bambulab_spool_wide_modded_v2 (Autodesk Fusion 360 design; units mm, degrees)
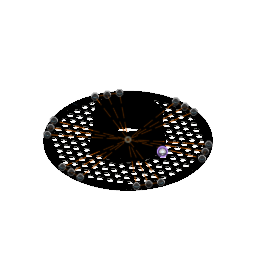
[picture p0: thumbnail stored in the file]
parameter "lattice_diameter" = 10.25
parameter "lattice_thickness" = 3.75
parameter "hole_diameter" = 3.5 comment "Hole Diameter of the rim"
base_mesh_feature "Base Mesh Feature"
convert_mesh "Convert Mesh" bodies "bambulab_spool_wide"
sketch "Sketch13" plane through (0, 0, -16.75) normal (0, 0, 1) x axis (-1, 0, 0)
  line L1 (92.6217, -5.7502) -> (99.4206, -5.9753)
  line L2 (92.483, -7.6633) -> (92.6217, -5.7502)
  line L3 (99.4206, -5.9753) -> (92.483, -7.6633)
  line L4 (0, 0) -> (-74.6153, -60.4003)
  line L5 (-89.6135, -34.4171) -> (0, 0)
  line L6 (-74.6153, -60.4003) -> (-89.6135, -34.4171)
  line L7 (-15.0006, -94.8162) -> (0, 0)
  line L8 (15.0006, -94.8189) -> (-15.0006, -94.8162)
  line L9 (0, 0) -> (15.0006, -94.8189)
  line L10 (0, 0) -> (74.6129, -60.399)
  line L11 (0, 0) -> (89.6159, -34.4185)
  line L12 (74.6129, -60.399) -> (89.6159, -34.4185)
  line L13 (89.6135, 34.4171) -> (0, 0)
  line L14 (74.6153, 60.4003) -> (89.6135, 34.4171)
  line L15 (0, 0) -> (74.6153, 60.4003)
  line L16 (0, 0) -> (-15.0006, 94.8189)
  line L17 (15.0006, 94.8162) -> (-15.0006, 94.8189)
  line L18 (0, 0) -> (15.0006, 94.8162)
  line L19 (0, 0) -> (-89.6159, 34.4185)
  line L20 (-89.6159, 34.4185) -> (-74.6129, 60.399)
  line L21 (0, 0) -> (-74.6129, 60.399)
  line L22 (0, 0) -> (-82.1144, 47.4088)
  line L23 (0, 0) -> (0, 94.8175)
  line L24 (0, 0) -> (82.1144, 47.4087)
  line L25 (0, 0) -> (82.1144, -47.4088)
  line L26 (0, 0) -> (0, -94.8175)
  line L27 (0, 0) -> (-82.1144, -47.4087)
  circle C1 centre (15.0006, -94.8189) radius 2
  circle C2 centre (-15.0006, -94.8162) radius 2
  circle C3 centre (89.6159, -34.4185) radius 2
  circle C4 centre (74.6153, 60.4003) radius 2
  circle C5 centre (-15.0006, 94.8189) radius 2
  circle C6 centre (-89.6159, 34.4185) radius 2
  circle C7 centre (-74.6153, -60.4003) radius 2
  circle C8 centre (74.6129, -60.399) radius 2
  circle C9 centre (89.6135, 34.4171) radius 2
  circle C10 centre (15.0006, 94.8162) radius 2
  circle C11 centre (-74.6129, 60.399) radius 2
  circle C12 centre (-89.6135, -34.4171) radius 2
  point P1 (0, 0)
  point P7 (0, 0)
  point P12 (-74.6153, -60.4003)
  point P18 (-74.6153, -60.4003)
  point P19 (0, 0)
  point P17 (-89.6135, -34.4171)
  point P20 (-89.6135, -34.4171)
  point P21 (-74.6153, -60.4003)
  point P22 (-82.1144, -47.4087)
  point P23 (0, 0)
  point P6 (-15.0006, -94.8162)
  point P24 (-15.0006, -94.8162)
  point P5 (15.0006, -94.8189)
  point P25 (15.0006, -94.8189)
  point P26 (0, 0)
  point P13 (74.6129, -60.399)
  point P27 (74.6129, -60.399)
  point P28 (0, 0)
  point P8 (89.6159, -34.4185)
  point P29 (89.6159, -34.4185)
  point P30 (0, 0)
  point P31 (89.6159, -34.4185)
  point P14 (89.6135, 34.4171)
  point P32 (89.6135, 34.4171)
  point P9 (74.6153, 60.4003)
  point P33 (74.6153, 60.4003)
  point P34 (0, 0)
  point P10 (-15.0006, 94.8189)
  point P35 (-15.0006, 94.8189)
  point P36 (0, 0)
  point P37 (-15.0006, 94.8189)
  point P15 (15.0006, 94.8162)
  point P38 (15.0006, 94.8162)
  point P39 (15.0006, 94.8162)
  point P40 (0, 0)
  point P11 (-89.6159, 34.4185)
  point P41 (-89.6159, 34.4185)
  point P42 (0, 0)
  point P16 (-74.6129, 60.399)
  point P43 (-74.6129, 60.399)
  point P44 (-89.6159, 34.4185)
  point P45 (0, -94.8175)
  point P46 (82.1144, -47.4088)
  point P47 (82.1144, 47.4087)
  point P48 (0, 94.8175)
  point P49 (-82.1144, 47.4088)
  point P50 (-82.1144, 47.4088)
  point P51 (0, 0)
  point P52 (0, 94.8175)
  point P53 (0, 0)
  point P54 (82.1144, 47.4087)
  point P55 (82.1144, -47.4088)
  point P56 (0, -94.8175)
  point P57 (-82.1144, -47.4087)
  point P58 (0, 0)
  coincident P1 P7
  coincident P12 P18
  coincident P7 P19
  coincident P17 P20
  coincident P12 P21
  midpoint L6 P22
  coincident P7 P23
  coincident P6 P24
  coincident P5 P25
  coincident P1 P26
  coincident P13 P27
  coincident P1 P28
  coincident P8 P29
  coincident P7 P30
  coincident P8 P31
  coincident P14 P32
  coincident P9 P33
  coincident P1 P34
  coincident P10 P35
  coincident P1 P36
  coincident P10 P37
  coincident P15 P38
  coincident P15 P39
  coincident P1 P40
  coincident P11 P41
  coincident P7 P42
  coincident P16 P43
  coincident P11 P44
  midpoint L8 P45
  midpoint L12 P46
  midpoint L14 P47
  midpoint L17 P48
  midpoint L20 P49
  coincident P49 P50
  coincident P1 P51
  coincident P48 P52
  coincident P7 P53
  coincident P47 P54
  coincident P46 P55
  coincident P45 P56
  coincident P22 P57
  coincident P1 P58
  dimension "d48" diameter C1 = 4
  dimension "d49" diameter C2 = 4
  dimension "d51" C-Pattern1-Angle = 360
  dimension "d53" C-Pattern2-Angle = 360
extrude "Extrude5" cut sketch "Sketch13" profile of C3 C4 C6 C7 C8 C9 C11 C12 against normal blind 25
sketch "Sketch14" plane through (0, 0, -17.85) normal (0, 0, 1) x axis (-1, 0, 0)
  line L1 (-23.297, 37.7968) -> (-24.4167, 37.0834)
  line L2 (-2.5625, 4.4384) -> (2.5625, 4.4384)
  line L3 (-5.125, 0) -> (-2.5625, 4.4384)
  line L4 (-2.5625, -4.4384) -> (-5.125, 0)
  line L5 (2.5625, -4.4384) -> (-2.5625, -4.4384)
  line L6 (5.125, 0) -> (2.5625, -4.4384)
  line L7 (2.5625, 4.4384) -> (5.125, 0)
  line L8 (5.125, -12.6268) -> (2.5625, -17.0651)
  line L9 (2.5625, -8.1884) -> (5.125, -12.6268)
  line L10 (-2.5625, -8.1884) -> (2.5625, -8.1884)
  line L11 (-5.125, -12.6268) -> (-2.5625, -8.1884)
  line L12 (-2.5625, -17.0651) -> (-5.125, -12.6268)
  line L13 (2.5625, -17.0651) -> (-2.5625, -17.0651)
  line L14 (0, -45.5) -> (0, 45.5)
  line L15 (-37, 0) -> (37, 0)
  line L16 (16.0601, -6.3134) -> (13.4976, -10.7518)
  line L17 (13.4976, -1.875) -> (16.0601, -6.3134)
  line L18 (8.3726, -1.875) -> (13.4976, -1.875)
  line L19 (5.8101, -6.3134) -> (8.3726, -1.875)
  line L20 (8.3726, -10.7518) -> (5.8101, -6.3134)
  line L21 (13.4976, -10.7518) -> (8.3726, -10.7518)
  line L22 (13.4976, 10.7518) -> (16.0601, 6.3134)
  line L23 (8.3726, 10.7518) -> (13.4976, 10.7518)
  line L24 (5.8101, 6.3134) -> (8.3726, 10.7518)
  line L25 (8.3726, 1.875) -> (5.8101, 6.3134)
  line L26 (13.4976, 1.875) -> (8.3726, 1.875)
  line L27 (16.0601, 6.3134) -> (13.4976, 1.875)
  line L28 (-5.125, -17.0651) -> (-5.125, 10.7518)
  line L29 (16.0601, -17.0651) -> (16.0601, 10.7518)
  line L30 (-5.125, 10.7518) -> (16.0601, 10.7518)
  line L31 (-5.125, -17.0651) -> (16.0601, -17.0651)
  line L32 (-92.4279, -85.5158) -> (-89.8654, -89.9542)
  line L33 (-89.8654, -89.9542) -> (-92.4279, -94.3926)
  line L34 (-92.4279, -94.3926) -> (-97.5529, -94.3926)
  line L35 (-97.5529, -94.3926) -> (-100.1154, -89.9542)
  line L36 (-100.1154, -89.9542) -> (-97.5529, -85.5158)
  line L37 (-97.5529, -85.5158) -> (-92.4279, -85.5158)
  line L38 (-92.4279, -98.1426) -> (-89.8654, -102.581)
  line L39 (-97.5529, -98.1426) -> (-92.4279, -98.1426)
  line L40 (-100.1154, -102.581) -> (-97.5529, -98.1426)
  line L41 (-97.5529, -107.0194) -> (-100.1154, -102.581)
  line L42 (-92.4279, -107.0194) -> (-97.5529, -107.0194)
  line L43 (-89.8654, -102.581) -> (-92.4279, -107.0194)
  line L44 (-100.8005, -96.2676) -> (-103.363, -100.706)
  line L45 (-103.363, -91.8292) -> (-100.8005, -96.2676)
  line L46 (-108.488, -91.8292) -> (-103.363, -91.8292)
  line L47 (-111.0505, -96.2676) -> (-108.488, -91.8292)
  line L48 (-108.488, -100.706) -> (-111.0505, -96.2676)
  line L49 (-103.363, -100.706) -> (-108.488, -100.706)
  line L50 (-108.488, -104.456) -> (-103.363, -104.456)
  line L51 (-103.363, -104.456) -> (-100.8005, -108.8944)
  line L52 (-100.8005, -108.8944) -> (-103.363, -113.3327)
  line L53 (-103.363, -113.3327) -> (-108.488, -113.3327)
  line L54 (-108.488, -113.3327) -> (-111.0505, -108.8944)
  line L55 (-111.0505, -108.8944) -> (-108.488, -104.456)
  line L56 (-71.2428, -85.5158) -> (-68.6803, -89.9542)
  line L57 (-68.6803, -89.9542) -> (-71.2428, -94.3926)
  line L58 (-71.2428, -94.3926) -> (-76.3678, -94.3926)
  line L59 (-76.3678, -94.3926) -> (-78.9303, -89.9542)
  line L60 (-78.9303, -89.9542) -> (-76.3678, -85.5158)
  line L61 (-76.3678, -85.5158) -> (-71.2428, -85.5158)
  line L62 (-71.2428, -98.1426) -> (-68.6803, -102.581)
  line L63 (-76.3678, -98.1426) -> (-71.2428, -98.1426)
  line L64 (-78.9303, -102.581) -> (-76.3678, -98.1426)
  line L65 (-76.3678, -107.0194) -> (-78.9303, -102.581)
  line L66 (-71.2428, -107.0194) -> (-76.3678, -107.0194)
  line L67 (-68.6803, -102.581) -> (-71.2428, -107.0194)
  line L68 (-79.6154, -96.2676) -> (-82.1779, -100.706)
  line L69 (-82.1779, -91.8292) -> (-79.6154, -96.2676)
  line L70 (-87.3029, -91.8292) -> (-82.1779, -91.8292)
  line L71 (-89.8654, -96.2676) -> (-87.3029, -91.8292)
  line L72 (-87.3029, -100.706) -> (-89.8654, -96.2676)
  line L73 (-82.1779, -100.706) -> (-87.3029, -100.706)
  line L74 (-87.3029, -104.456) -> (-82.1779, -104.456)
  line L75 (-82.1779, -104.456) -> (-79.6154, -108.8944)
  line L76 (-79.6154, -108.8944) -> (-82.1779, -113.3327)
  line L77 (-82.1779, -113.3327) -> (-87.3029, -113.3327)
  line L78 (-87.3029, -113.3327) -> (-89.8654, -108.8944)
  line L79 (-89.8654, -108.8944) -> (-87.3029, -104.456)
  line L80 (-50.0577, -85.5158) -> (-47.4952, -89.9542)
  line L81 (-47.4952, -89.9542) -> (-50.0577, -94.3926)
  line L82 (-50.0577, -94.3926) -> (-55.1827, -94.3926)
  line L83 (-55.1827, -94.3926) -> (-57.7452, -89.9542)
  line L84 (-57.7452, -89.9542) -> (-55.1827, -85.5158)
  line L85 (-55.1827, -85.5158) -> (-50.0577, -85.5158)
  line L86 (-50.0577, -98.1426) -> (-47.4952, -102.581)
  line L87 (-55.1827, -98.1426) -> (-50.0577, -98.1426)
  line L88 (-57.7452, -102.581) -> (-55.1827, -98.1426)
  line L89 (-55.1827, -107.0194) -> (-57.7452, -102.581)
  line L90 (-50.0577, -107.0194) -> (-55.1827, -107.0194)
  line L91 (-47.4952, -102.581) -> (-50.0577, -107.0194)
  line L92 (-58.4303, -96.2676) -> (-60.9928, -100.706)
  line L93 (-60.9928, -91.8292) -> (-58.4303, -96.2676)
  line L94 (-66.1178, -91.8292) -> (-60.9928, -91.8292)
  line L95 (-68.6803, -96.2676) -> (-66.1178, -91.8292)
  line L96 (-66.1178, -100.706) -> (-68.6803, -96.2676)
  line L97 (-60.9928, -100.706) -> (-66.1178, -100.706)
  line L98 (-66.1178, -104.456) -> (-60.9928, -104.456)
  line L99 (-60.9928, -104.456) -> (-58.4303, -108.8944)
  line L100 (-58.4303, -108.8944) -> (-60.9928, -113.3327)
  line L101 (-60.9928, -113.3327) -> (-66.1178, -113.3327)
  line L102 (-66.1178, -113.3327) -> (-68.6803, -108.8944)
  line L103 (-68.6803, -108.8944) -> (-66.1178, -104.456)
  line L104 (-28.8726, -85.5158) -> (-26.3101, -89.9542)
  line L105 (-26.3101, -89.9542) -> (-28.8726, -94.3926)
  line L106 (-28.8726, -94.3926) -> (-33.9976, -94.3926)
  line L107 (-33.9976, -94.3926) -> (-36.5601, -89.9542)
  line L108 (-36.5601, -89.9542) -> (-33.9976, -85.5158)
  line L109 (-33.9976, -85.5158) -> (-28.8726, -85.5158)
  line L110 (-28.8726, -98.1426) -> (-26.3101, -102.581)
  line L111 (-33.9976, -98.1426) -> (-28.8726, -98.1426)
  line L112 (-36.5601, -102.581) -> (-33.9976, -98.1426)
  line L113 (-33.9976, -107.0194) -> (-36.5601, -102.581)
  line L114 (-28.8726, -107.0194) -> (-33.9976, -107.0194)
  line L115 (-26.3101, -102.581) -> (-28.8726, -107.0194)
  line L116 (-37.2452, -96.2676) -> (-39.8077, -100.706)
  line L117 (-39.8077, -91.8292) -> (-37.2452, -96.2676)
  line L118 (-44.9327, -91.8292) -> (-39.8077, -91.8292)
  line L119 (-47.4952, -96.2676) -> (-44.9327, -91.8292)
  line L120 (-44.9327, -100.706) -> (-47.4952, -96.2676)
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  point P1 (0, 0)
  point P4 (0, 0)
  point P5 (0, 0)
  point P6 (0, 0)
  point P13 (0, 0)
  point P20 (0, -12.6268)
  point P9 (-5.125, 0)
  point P26 (16.0601, -6.3134)
  point P41 (16.0601, -17.0651)
  point P42 (-5.125, -17.0651)
  point P39 (-5.125, 10.7518)
  point P40 (16.0601, 10.7518)
  point P12 (5.125, 0)
  point P7 (2.5625, 4.4384)
  point P10 (-2.5625, -4.4384)
  point P15 (5.125, -12.6268)
  point P18 (-5.125, -12.6268)
  point P14 (2.5625, -17.0651)
  point P17 (-2.5625, -8.1884)
  point P29 (5.8101, -6.3134)
  point P32 (16.0601, 6.3134)
  point P35 (5.8101, 6.3134)
  coincident P1 P4
  coincident P1 P5
  coincident P1 P6
  coincident P5 P13
  vertical L14
  horizontal L15
  coincident P1 L14
  midpoint P4 L15
  midpoint P1 L14
  coincident P20 L14
  parallel L5 L15
  parallel L15 L21
  parallel L15 L26
  vertical L28
  vertical L29
  coincident P9 L28
  coincident P26 L29
  perpendicular L29 L30
  horizontal L31
  collinear L23 L30
  collinear L13 L31
  coincident L29 P41
  coincident L28 P42
  coincident P39 L30
  coincident L29 P40
  dimension "d56" diameter = 183.4
  dimension "d57" diameter = 89
  dimension "d62" diameter = 179.65 (= "183.4 mm - lattice_thickness")
  dimension "d63" distance P9 P12 = 10.25 (= "lattice_diameter")
  dimension "d64" distance P7 P10 = 10.25 (= "lattice_diameter")
  dimension "d65" distance P15 P18 = 10.25 (= "lattice_diameter")
  dimension "d66" distance P14 P17 = 10.25 (= "lattice_diameter")
  dimension "d67" distance L5 L10 = 3.75 (= "lattice_thickness")
  dimension "d68" distance P26 P29 = 10.25 (= "lattice_diameter")
  dimension "d69" distance L6 L19 = 3.75 (= "lattice_thickness")
  dimension "d70" distance L9 L20 = 3.75 (= "lattice_thickness")
  dimension "d71" distance P32 P35 = 10.25 (= "lattice_diameter")
  dimension "d72" distance L18 L26 = 3.75 (= "lattice_thickness")
  dimension "d73" distance L7 L25 = 3.75 (= "lattice_thickness")
  dimension "d74" distance P41 P42 = 21.1851
  dimension "d75" distance P40 P41 = 27.8169
  dimension "d78" R-Pattern1-uDistance = 21.1851
  dimension "d79" R-Pattern1-vDistance = 24.0669 (= "27.816899 mm - lattice_thickness")
extrude "Extrude6" cut sketch "Sketch14" distance 30
work_plane "WorkPlane3" RotateAngle 45
sketch "Sketch16" plane through (27.1973, 30.4798, 1.2) normal (0.7071, 0.7071, -0.0003) x axis (-0.0041, 0.0036, -1)
  line L1 (17.7883, -26.5886) -> (17.7779, -28.5173)
  circle C1 centre (17.5808, -27.9755) radius 1.1
  point P2 (17.5808, -27.9755)
  dimension "d84" diameter C1 = 2.2
  dimension "d85" distance P2 L1 = 0.2
extrude "Extrude7" cut sketch "Sketch16" profile of C1 against normal blind 13
work_plane "WorkPlane4" RotateAngle 120
sketch "Sketch17" plane through (37.7529, -15.5941, 1.2) normal (0.6096, -0.7926, -0.0143) x axis (0.0109, 0.0265, -0.9996)
  line L1 (19.3005, 6.8332) -> (19.2658, 5.9127)
  circle C1 centre (17.9921, 7.9641) radius 1.1
  point P2 (17.9921, 7.9641)
  dimension "d89" diameter C1 = 2.2
  dimension "d93" distance P2 L1 = 1.35
extrude "Extrude8" cut sketch "Sketch17" profile of C1 against normal blind 10.5
sketch "Sketch18" plane through (0, 0, -17.85) normal (0, 0, 1) x axis (-1, 0, 0)
  line L1 (-48.5558, 4.4764) -> (-47.9524, 5.5214)
  line L2 (-40.6099, 4.4226) -> (-48.5558, 4.4764)
  line L3 (-40.4572, 5.6509) -> (-40.6099, 4.4226)
  line L4 (-47.9524, 5.5214) -> (-40.4572, 5.6509)
  line L5 (-44, 2.7549) -> (-40.755, 2.7549)
  line L6 (-44, -2.9962) -> (-44, 2.7549)
  line L7 (-40.738, -2.9962) -> (-44, -2.9962)
  circle C1 centre (0, 0) radius 40.848
  point P1 (0, 0)
  point P6 (0, 0)
  point P7 (-40.755, 2.7549)
  point P10 (-40.738, -2.9962)
  coincident P1 P6
  coincident C1 P7
  horizontal L5
  perpendicular L5 L6
  coincident C1 P10
  perpendicular L6 L7
  dimension "d94" diameter C1 = 81.696
extrude "Extrude9" cut sketch "Sketch18" profile of C1 L5 L6 L7 along normal blind 9
sketch "Sketch19" plane through (7.5003, 47.4081, -16.75) normal (-0.6984, 0.1105, 0.7071) x axis (0.1563, 0.9877, 0)
  circle C1 centre (48, 0) radius 1.75
  dimension "d101" diameter C1 = 3.5 (= "hole_diameter")
extrude "Extrude11" add sketch "Sketch13" profile of C1 C2 C5 C10 against normal blind 3.6
work_plane "WorkPlane8" RotateAngle 45
sketch "Sketch20" plane through (44.8068, 17.2086, -16.75) normal (0.2535, -0.6601, 0.7071) x axis (0.9335, 0.3585, 0)
  circle C1 centre (48, 0) radius 1.75
  dimension "d107" diameter C1 = 3.5 (= "hole_diameter")
extrude "Extrude12" new body sketch "Sketch20" distance 20
work_plane "WorkPlane9" RotateAngle 45
sketch "Sketch22" plane through (37.3076, 30.2002, -16.75) normal (-0.4449, 0.5496, 0.7071) x axis (-0.7773, -0.6292, 0)
  circle C1 centre (-48, 0) radius 1.75
  dimension "d111" diameter C1 = 3.5 (= "hole_diameter")
extrude "Extrude13" new body sketch "Sketch22" distance 20
circular_pattern "C-Pattern1" TotalAngle 360
combine "Combine1"
named bodies: "bambulab_spool_wide"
